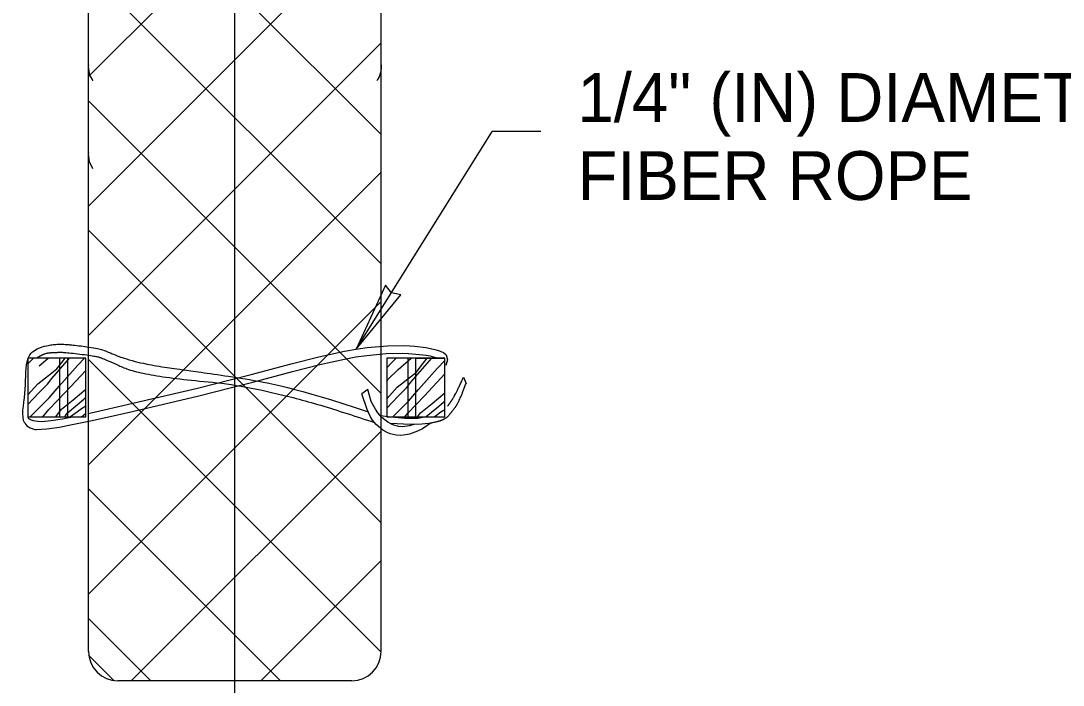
# Model space of a CAD drawing. Extents: x 99862 to 103680, y 99470 to 102076.
# Drawn here: x 101453 to 101794.9, y 100744.2 to 100962.1 of the extents above; entities that cross this region are included whole.
import ezdxf

# ---------------------------------------------------------------- set-up
doc = ezdxf.new("R2010")
doc.units = 0
for name, color, linetype in [('Level 10', 7, 'Continuous'), ('Level 15', 7, 'Continuous'), ('Level 20', 7, 'Continuous'), ('Level 3', 7, 'Continuous'), ('Level 4', 7, 'Continuous'), ('Level 6', 7, 'Continuous'), ('Level 8', 7, 'Continuous')]:
    doc.layers.add(name, color=color, linetype=linetype)

msp = doc.modelspace()

# ---------------------------------------------------------------- linework, layer by layer
at = {"layer": 'Level 10'}
msp.add_line((101523.17, 100717.05), (101523.17, 101320.79), dxfattribs=at)
at = {"layer": 'Level 15'}
for p in [(101562.99, 100854.45), (101623.59, 100925.83)]:
    msp.add_line(p, (101607.59, 100925.83), dxfattribs=at)
msp.add_lwpolyline([(101562.99, 100854.45), (101577.63, 100872.22), (101574.54, 100872.91), (101572.56, 100875.39)], close=True, dxfattribs=at)
at = {"layer": 'Level 3'}
for p, q in [((101455.27, 100851.46), (101455.27, 100832.25)), ((101455.27, 100849.58), (101456.8, 100851.11)), ((101456.8, 100851.11), (101457.15, 100851.46)), ((101459, 100848.91), (101461.92, 100851.46)), ((101463.14, 100844.76), (101468.98, 100851.46)), ((101465.81, 100832.25), (101465.81, 100851.46)), ((101468.29, 100851.46), (101468.29, 100832.25)), ((101474.34, 100832.25), (101474.34, 100851.46)), ((101474.34, 100851.46), (101474.35, 100851.46)), ((101573, 100851.46), (101573, 100832.25)), ((101574.62, 100849.95), (101576.13, 100851.46)), ((101576.82, 100847.75), (101581.06, 100851.46)), ((101580.02, 100832.25), (101580.02, 100851.46)), ((101580.96, 100843.61), (101587.81, 100851.46)), ((101582.5, 100851.46), (101582.5, 100832.25)), ((101592.07, 100832.25), (101592.07, 100851.46)), ((101592.07, 100851.46), (101592.08, 100851.46)), ((101573, 100848.33), (101574.62, 100849.95)), ((101585.41, 100839.15), (101592.08, 100846.28)), ((101587.93, 100836.64), (101592.08, 100840.15)), ((101590.74, 100833.82), (101592.08, 100834.64))]:
    msp.add_line(p, q, dxfattribs=at)
for points in [[(101474.35, 100851.46), (101474.34, 100851.46), (101455.27, 100851.46)], [(101456.24, 100851.46), (101456.24, 100851.46), (101456.24, 100851.46)], [(101462.1, 100845.81), (101464.83, 100847.97), (101466.89, 100850.61), (101467.57, 100851.46)], [(101465.58, 100842.33), (101471.7, 100849.22), (101473.87, 100851.46)], [(101592.08, 100851.46), (101592.07, 100851.46), (101573, 100851.46)], [(101592.08, 100851.46), (101592.07, 100851.46), (101573, 100851.46)], [(101579.92, 100844.65), (101582.65, 100846.81), (101584.71, 100849.45), (101586.3, 100851.46)], [(101582.5, 100851.46), (101582.5, 100851.46), (101592.07, 100851.46)], [(101573, 100843.85), (101573.49, 100844.61), (101576.82, 100847.75)], [(101583.4, 100841.17), (101589.52, 100848.06), (101592.08, 100850.71)], [(101455.27, 100839.41), (101458.58, 100843.07), (101462.1, 100845.81)], [(101455.27, 100836.28), (101458.94, 100840.14), (101461.72, 100842.92), (101463.14, 100844.76)], [(101467.6, 100840.31), (101474.28, 100847.46)], [(101573, 100838.15), (101576.4, 100841.91), (101579.92, 100844.65)], [(101456.09, 100832.25), (101462.31, 100838.48), (101465.58, 100842.33)], [(101470.11, 100837.79), (101474.26, 100841.31), (101474.28, 100841.33)], [(101573, 100835.03), (101576.76, 100838.98), (101579.54, 100841.76), (101580.96, 100843.61)], [(101575.06, 100832.25), (101580.13, 100837.32), (101583.4, 100841.17)], [(101460.23, 100832.25), (101462.13, 100834.6), (101467.6, 100840.31)], [(101464.45, 100832.25), (101464.46, 100832.28), (101466.3, 100834.7), (101470.11, 100837.79)], [(101471.59, 100836.31), (101473.7, 100838.04), (101474.28, 100838.64)], [(101578.98, 100832.25), (101579.95, 100833.45), (101585.41, 100839.15)], [(101589.41, 100835.16), (101591.51, 100836.88), (101592.08, 100837.46)], [(101467.4, 100832.25), (101468.17, 100833.48), (101471.59, 100836.31)], [(101469.29, 100832.25), (101469.33, 100832.32), (101471.54, 100833.95), (101472.93, 100834.98)], [(101472.93, 100834.98), (101474.28, 100835.81)], [(101583.13, 100832.25), (101584.12, 100833.55), (101587.93, 100836.64)], [(101585.95, 100832.25), (101585.99, 100832.32), (101589.41, 100835.16)], [(101455.27, 100832.25), (101474.34, 100832.25), (101474.35, 100832.25)], [(101456.24, 100832.25), (101456.24, 100832.25), (101456.24, 100832.25)], [(101472.86, 100832.25), (101473.63, 100832.93), (101474.28, 100833.41)], [(101573, 100832.25), (101592.07, 100832.25), (101592.08, 100832.25)], [(101588.63, 100832.25), (101589.36, 100832.79), (101590.74, 100833.82)], [(101592.08, 100832.25), (101592.08, 100832.25), (101592.08, 100832.25)]]:
    msp.add_lwpolyline(points, dxfattribs=at)
at = {"layer": 'Level 4'}
msp.add_line((101566.81, 100841.22), (101564.85, 100839.72), dxfattribs=at)
for points in [[(101475.13, 100833.36), (101476.08, 100833.57), (101480.33, 100834.52), (101489.78, 100836.66), (101510.9, 100841.64), (101521.64, 100844.34), (101528.58, 100846.16), (101541.71, 100849.64), (101550.79, 100851.93), (101559.13, 100853.76), (101562.99, 100854.45), (101566.64, 100854.96), (101573.25, 100855.53), (101578.94, 100855.58), (101582.19, 100855.4), (101585.84, 100854.96), (101587.36, 100854.69), (101588.83, 100854.35), (101589.68, 100854.11), (101591.08, 100853.57), (101591.65, 100853.27), (101592.56, 100852.59), (101592.97, 100850.92), (101592.38, 100849.06)], [(101454.31, 100830.17), (101454.97, 100829.27), (101456.03, 100828.58), (101457.58, 100828.09), (101458.06, 100828.07), (101461.55, 100828.27), (101465.68, 100828.87), (101468.79, 100829.45), (101475.86, 100830.95), (101480.31, 100831.93), (101490.05, 100834.11), (101511.39, 100839.13), (101522.13, 100841.82), (101529.05, 100843.63), (101542.07, 100847.09), (101551.02, 100849.37), (101559.18, 100851.18), (101562.93, 100851.87), (101566.45, 100852.38), (101572.78, 100852.96), (101578.14, 100853.07), (101580.21, 100853), (101583.76, 100852.71), (101585.9, 100852.43), (101587.21, 100852.2), (101587.96, 100852.03), (101589.16, 100851.67), (101589.53, 100851.46)], [(101598.2, 100845.2), (101599.02, 100843.17)], [(101581.92, 100829.74), (101580.46, 100829.23), (101578.2, 100828.96), (101577.02, 100829.05), (101575.4, 100829.46), (101574.58, 100829.8), (101573.33, 100830.51), (101571.44, 100832.04), (101570.1, 100833.58), (101569.32, 100834.73), (101567.91, 100837.22), (101566.81, 100841.22)], [(101587.75, 100830.36), (101587.57, 100830.21), (101584.72, 100828.34), (101583.09, 100827.49), (101580.44, 100826.53), (101578.57, 100826.19), (101577.61, 100826.13), (101576.16, 100826.2), (101574.19, 100826.65), (101573.2, 100827.05), (101571.72, 100827.87), (101569.53, 100829.69), (101568.33, 100831.13), (101567.68, 100832.23), (101566.58, 100834.66), (101564.85, 100839.72)], [(101455.27, 100832.25), (101455.54, 100831.63), (101456.39, 100831.23), (101457.04, 100831.03), (101458.55, 100830.79), (101459.85, 100830.75), (101462.93, 100830.98), (101466.64, 100831.57), (101469.96, 100832.25)], [(101586.16, 100832.27), (101586.03, 100832.22), (101584.27, 100831.86), (101583.23, 100831.69), (101582, 100831.63), (101579, 100831.67), (101573.52, 100832.2), (101570.96, 100832.58)], [(101586.77, 100830.09), (101584.57, 100829.8), (101582.12, 100829.67), (101578.53, 100829.8), (101576.43, 100829.91), (101574.08, 100830.07)]]:
    msp.add_lwpolyline(points, dxfattribs=at)
for points, degree in [([(101454.31, 100830.17), (101453, 100832.41), (101454.93, 100839.59), (101454.17, 100851.85), (101458.49, 100854.84), (101461.65, 100855.64), (101463.35, 100855.9), (101463.9, 100855.95), (101464.98, 100856.03), (101465.53, 100856.05), (101466.72, 100856.04), (101467.36, 100856.01), (101468.89, 100855.89), (101469.81, 100855.8), (101472.85, 100855.46), (101475.18, 100855.15), (101478.48, 100854.6), (101479.65, 100854.29), (101481.91, 100853.39), (101482.77, 100853.01), (101484.99, 100852.09), (101486.4, 100851.55), (101490.69, 100850.33), (101493.56, 100849.65), (101501.42, 100848.28), (101506.45, 100847.67), (101525.31, 100844.98), (101542.8, 100841.93), (101566.98, 100833.9)], 3), ([(101458.13, 100851.46), (101460.56, 100853.13), (101464.52, 100853.38), (101467.47, 100853.42), (101477.72, 100852.14), (101479.98, 100851.35), (101493.13, 100845.55), (101534.98, 100841.97), (101568.93, 100830.41)], 2), ([(101593.01, 100835.73), (101594.24, 100837.42), (101595.58, 100839.63), (101598.2, 100845.2)], 2), ([(101592.98, 100832.24), (101594.84, 100834.38), (101597, 100837.61), (101599.02, 100843.17)], 2), ([(101586.77, 100830.09), (101589.9, 100830.74), (101591.51, 100831.31), (101592.98, 100832.24)], 2)]:
    msp.add_open_spline(points, degree=degree, dxfattribs=at)
at = {"layer": 'Level 6'}
for p, q in [((101475.17, 100943.79), (101571.17, 101039.79)), ((101475.17, 101020.79), (101571.17, 100924.79)), ((101475.17, 100901.35), (101571.17, 100997.35)), ((101475.17, 100978.35), (101571.17, 100882.35)), ((101475.2, 100858.93), (101571.17, 100954.9)), ((101476.35, 100942.81), (101476.55, 100942.43)), ((101570, 100942.81), (101569.79, 100942.43)), ((101475.17, 100935.91), (101571.17, 100839.91)), ((101476.35, 100914), (101476.55, 100913.62)), ((101475.17, 100816.46), (101571.17, 100912.46)), ((101475.17, 100893.47), (101571.17, 100797.47)), ((101475.17, 100774.02), (101571.17, 100870.02)), ((101475.17, 100851.03), (101571.17, 100755.03)), ((101489.45, 100745.86), (101571.17, 100827.58)), ((101475.17, 100808.59), (101537.9, 100745.86)), ((101531.89, 100745.86), (101571.17, 100785.14)), ((101475.17, 100766.14), (101495.46, 100745.86)), ((101475.17, 100754.08), (101483.56, 100745.7))]:
    msp.add_line(p, q, dxfattribs=at)
for points in [[(101475.17, 100947.71), (101475.13, 100947.15), (101475.16, 100946.37), (101475.46, 100944.79), (101475.84, 100943.74), (101476.35, 100942.81)], [(101571.17, 100947.71), (101571.21, 100947.15), (101571.18, 100946.37), (101570.88, 100944.79), (101570.51, 100943.74), (101570, 100942.81)], [(101475.17, 100918.9), (101475.13, 100918.34), (101475.16, 100917.56), (101475.46, 100915.99), (101475.84, 100914.93), (101476.35, 100914)]]:
    msp.add_lwpolyline(points, dxfattribs=at)
at = {"layer": 'Level 8'}
msp.add_line((101475.17, 100755.3), (101475.17, 101197.21), dxfattribs=at)
for points in [[(101571.17, 100755.46), (101571.17, 101197.21)], [(101561.57, 100745.7), (101554.87, 100745.7), (101550.99, 100745.7), (101546.82, 100745.7), (101542.4, 100745.7), (101537.78, 100745.7), (101532.99, 100745.7), (101528.11, 100745.7), (101523.17, 100745.7), (101518.24, 100745.7), (101513.35, 100745.7), (101508.57, 100745.7), (101503.94, 100745.7), (101499.52, 100745.7), (101495.35, 100745.7), (101484.78, 100745.7)]]:
    msp.add_lwpolyline(points, dxfattribs=at)
for centre, start, end in [((101484.78, 100755.3), 180, 270), ((101561.57, 100755.3), 270, 0)]:
    msp.add_arc(centre, 9.6, start, end, dxfattribs=at)

# ---------------------------------------------------------------- texts
at = {"layer": 'Level 20'}
for s, p in [('1/4" (IN) DIAMETER NATURAL ', (101635.59, 100928.95)), ('FIBER ROPE', (101635.59, 100903.35))]:
    msp.add_text(s, height=16, dxfattribs=at).set_placement(p)

doc.saveas('drawing.dxf')
